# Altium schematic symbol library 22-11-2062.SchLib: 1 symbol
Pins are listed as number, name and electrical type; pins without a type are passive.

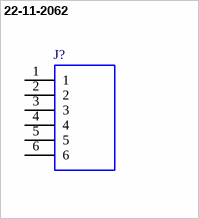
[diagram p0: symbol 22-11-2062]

## 22-11-2062
designator J?
2.54mm,header,KK,vert,Au,frictn lock,6w Molex KK Series, Series Number 6373, 2.54mm Pitch 6 Way 1 Row Straight PCB Header, Solder Termination; Geometry.Height: 10.92mm
footprint HDRV6W87P0X254_1X6_1509X635X1092P
pins: 1, 2, 3, 4, 5, 6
